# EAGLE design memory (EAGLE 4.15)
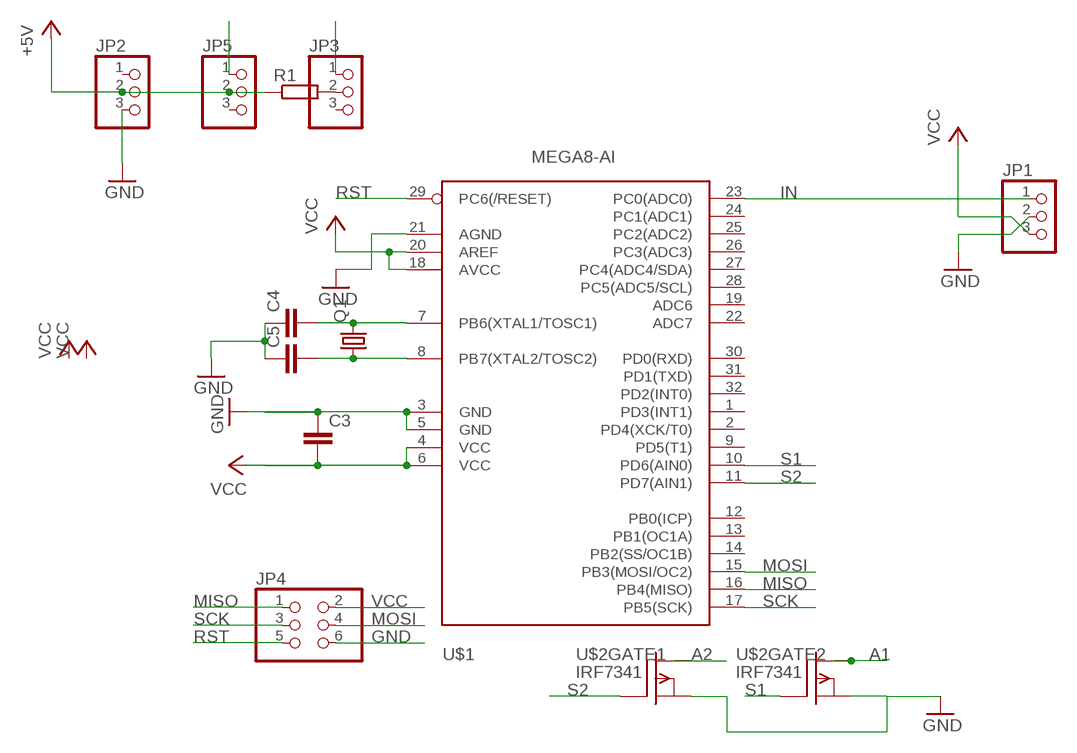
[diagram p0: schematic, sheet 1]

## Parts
C3  C-EUC1206K  [C1206K]
C4  C-EUC1206K  [C1206K]
C5  C-EUC1206K  [C1206K]
JP1  PINHD-1X3  [1X03]
JP2  PINHD-1X3  [1X03]
JP3  PINHD-1X3  [1X03]
JP4  PINHD-2X3  [2X03]
JP5  PINHD-1X3  [1X03]
Q1  CRYTALHC49U-V  [HC49U-V]
R1  R-EU_R1206  [R1206]
U$1  MEGA8-AI  [TQFP32-08]
U$2  IRF7341  [SO-8]

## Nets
+5V: JP2.2 JP5.2 R1.1
A1: JP3.1 U$2.5(GATE2:D1) U$2.6(GATE2:D)
A2: JP5.1 U$2.7(GATE1:D1) U$2.8(GATE1:D)
GND: C3.1 C4.1 C5.1 JP1.2 JP2.3 JP4.6 U$1.3(GND) U$1.5(GND) U$1.21(AGND) U$2.1(GATE1:S) U$2.3(GATE2:S)
IN: JP1.1 U$1.23(PC0(ADC0))
MISO: JP4.1 U$1.16(PB4(MISO))
MOSI: JP4.4 U$1.15(PB3(MOSI/OC2))
N$1: C4.2 Q1.2 U$1.7(PB6(XTAL1/TOSC1))
N$2: C5.2 Q1.1 U$1.8(PB7(XTAL2/TOSC2))
N$7: JP3.2 R1.2
RST: JP4.5 U$1.29(PC6(/RESET))
S1: U$1.10(PD6(AIN0)) U$2.4(GATE2:G)
S2: U$1.11(PD7(AIN1)) U$2.2(GATE1:G)
SCK: JP4.3 U$1.17(PB5(SCK))
VCC: C3.2 JP1.3 JP4.2 U$1.4(VCC) U$1.6(VCC) U$1.18(AVCC) U$1.20(AREF)
Unconnected: JP2.1 JP3.3 JP5.3 U$1.1(PD3(INT1)) U$1.2(PD4(XCK/T0)) U$1.9(PD5(T1)) U$1.12(PB0(ICP)) U$1.13(PB1(OC1A)) U$1.14(PB2(SS/OC1B)) U$1.19(ADC6) U$1.22(ADC7) U$1.24(PC1(ADC1)) U$1.25(PC2(ADC2)) U$1.26(PC3(ADC3)) U$1.27(PC4(ADC4/SDA)) U$1.28(PC5(ADC5/SCL)) U$1.30(PD0(RXD)) U$1.31(PD1(TXD)) U$1.32(PD2(INT0))

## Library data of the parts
C3-C5 = rcl:C-EU: CAPACITOR, European symbol
JP1-JP3 JP5 = pinhead:PINHD-1X3: PIN HEADER
JP4 = pinhead:PINHD-2X3: PIN HEADER
Q1 = crystal:CRYTAL: CRYSTAL
R1 = rcl:R-EU_: RESISTOR, European symbol
U$1 = avr:MEGA8: MICROCONTROLLER 8 Kbytes FLASH 1 kbytes SRAM 512 bytes EEPROM USART 6-channel 10 bit ADC 2-channel 8 bit ADC
U$2 = transistor-fet:IRF7341

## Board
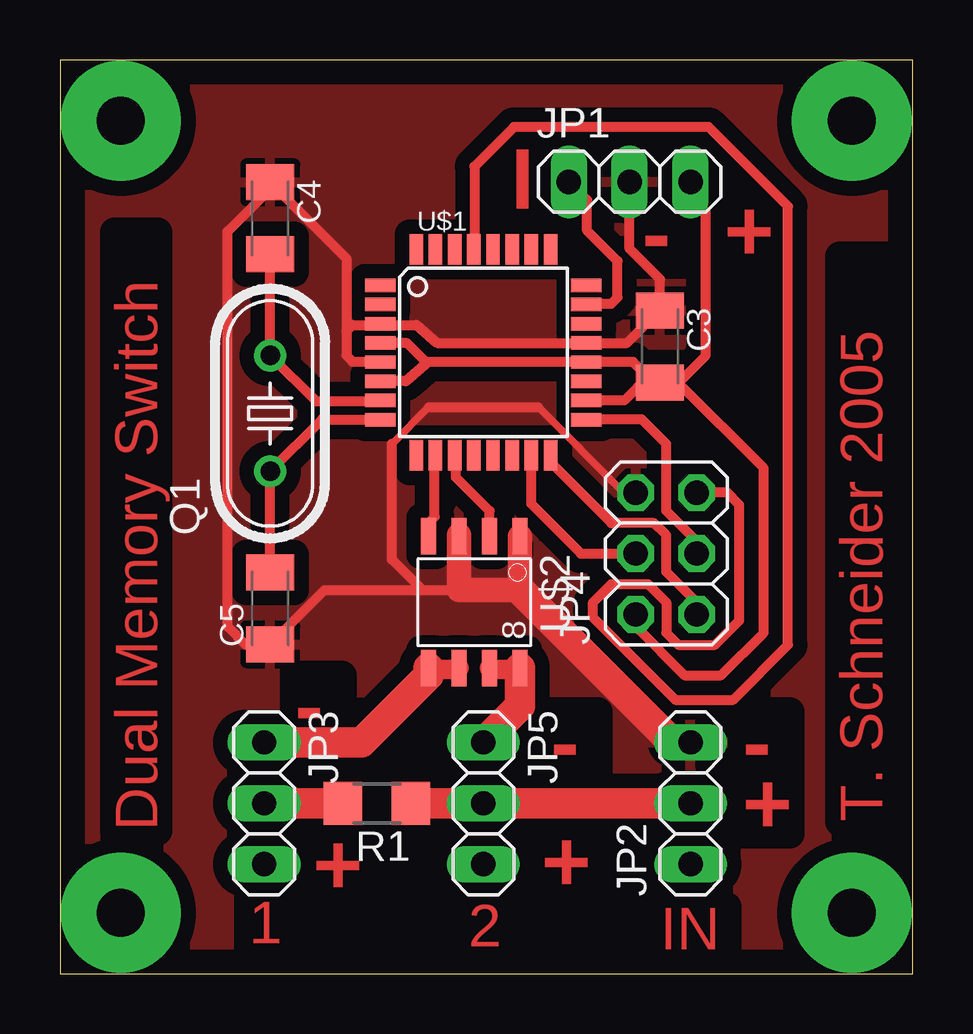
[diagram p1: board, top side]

Size 35.56 x 38.1 mm. Coordinates in mm from the lower left corner, seen from the top.
Outline: 0,0 35.56,0 35.56,38.1 0,38.1 0,0
Copper layers (1*16): Top 0.035mm / dielectric 1.5mm / Bottom 0.035mm
Design rules "default": minimum track width 10mil, minimum drill 24mil, track to track 10mil, track to pad 10mil, pad to pad 8mil, via to via 8mil, smd to smd 8mil, copper to edge 40mil, drill to drill 8mil, minimum pad ring 10mil, minimum via ring 8mil, stop-mask expansion 4mil, vias tented up to drill 0mil, thermal gap 10mil

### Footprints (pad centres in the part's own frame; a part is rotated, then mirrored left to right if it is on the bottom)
C1206K = smd 1.5 x 2: 1 -1.5,0; 2 1.5,0
1X03 = drill 1.016 long: 1 -2.54,0; 2 0,0; 3 2.54,0
2X03 = drill 1.016 octagon: 1 -2.54,-1.27; 2 -2.54,1.27; 3 0,-1.27; 4 0,1.27; 5 2.54,-1.27; 6 2.54,1.27
HC49U-V = drill 0.813 round: 1 -2.413,0; 2 2.413,0
R1206 = smd 1.6 x 1.803: 1 -1.422,0; 2 1.422,0
TQFP32-08 = smd 1.27 x 0.559: 1 -4.293,2.8; 2 -4.293,2; 3 -4.293,1.2; 4 -4.293,0.4; 5 -4.293,-0.4; 6 -4.293,-1.2; 7 -4.293,-2; 8 -4.293,-2.8; 17 4.293,-2.8; 18 4.293,-2; 19 4.293,-1.2; 20 4.293,-0.4; 21 4.293,0.4; 22 4.293,1.2; 23 4.293,2; 24 4.293,2.8 | smd 0.559 x 1.27: 9 -2.8,-4.293; 10 -2,-4.293; 11 -1.2,-4.293; 12 -0.4,-4.293; 13 0.4,-4.293; 14 1.2,-4.293; 15 2,-4.293; 16 2.8,-4.293; 25 2.8,4.293; 26 2,4.293; 27 1.2,4.293; 28 0.4,4.293; 29 -0.4,4.293; 30 -1.2,4.293; 31 -2,4.293; 32 -2.8,4.293
SO-8 = smd 1.524 x 0.61: 1 -2.743,1.27; 2 -2.743,0; 3 -2.743,-1.27; 4 -2.743,-2.54; 5 2.743,-2.54; 6 2.743,-1.27; 7 2.743,0; 8 2.743,1.27

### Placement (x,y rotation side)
C3  25.02,26.16 270 top
C4  8.76,31.5 270 top
C5  8.76,15.24 90 top
JP1  23.75,33.02 0 top
JP2  26.29,7.11 90 top
JP3  8.51,7.11 270 top
JP4  25.27,17.53 90 top
JP5  17.65,7.11 270 top
Q1  8.76,23.37 90 top
R1  13.21,7.11 180 top
U$1  17.65,25.91 0 top
U$2  17.91,15.49 270 top

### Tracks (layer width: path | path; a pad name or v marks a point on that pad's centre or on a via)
+5V
  Top 1.27: JP5.2 JP2.2 | R1.1 JP5.2 | JP5.2 17.65,6.99
A1
  Top 0.813: U$2.6 16.59,12.7 15.42,12.7 U$2.5
  Top 1.27: U$2.5 15.37,12.45 12.57,9.65 JP3.1
A2
  Top 0.813: U$2.7 17.96,12.7 19.13,12.7 U$2.8
  Top 1.27: JP5.1 19.18,11.18 U$2.8
GND
  Top 0.305: 13.84,22.1 15.37,23.62 | 19.94,23.62 23.49,20.07
  Top 0.406: C3.1 24.51,27.69 24.53,27.66 | 23.49,20.07 JP4.6 | 15.37,23.62 19.94,23.62 | 13.84,22.1 13.84,17.27 15.11,16 | 15.11,16 16.64,16 | 13.34,27.05 13.36,27.15 U$1.3 | 13.48,25.51 U$1.5 13.34,25.53 12.19,25.53 11.94,25.78 11.94,26.8 | 24.53,27.66 24.77,27.43 | C3.1 24.53,27.66 | 25.02,27.69 23.64,26.31 U$1.21 15.73,26.31 14.86,27.05 13.34,27.05 | JP1.2 23.75,30.23 25.02,28.96 25.02,27.69 | C3.1 25.02,27.43 25.27,27.18 25.27,27.43 25.02,27.69 | 25.02,27.69 C3.1 | 13.34,27.05 13.34,27.13 U$1.3 | 15.11,16 11.03,16 C5.1 8.66,13.74 8.64,13.72 7.75,13.72 6.99,14.48 6.99,30.95 8.9,32.86 C4.1 11.94,29.82 11.94,26.8 | 11.94,26.8 12.19,27.05 13.34,27.05 | 13.34,27.05 13.36,27.08 U$1.3
  Top 1.016: U$2.1 19.18,16 16.64,16 U$2.3 16.64,18.29
  Top 1.27: 26.54,9.65 JP2.3 25.53,9.65 19.18,16
  pour Top (isolate 0.61): -1.14,39.24 -1.14,-0.89 37.46,-0.89 37.46,39.24
IN
  Top 0.406: U$1.23 21.97,27.94 22.99,27.94 23.24,28.19 23.24,29.72 21.97,30.99 21.97,32.26 JP1.1
MISO
  Top 0.406: U$1.16 20.45,21.33 22.99,18.8 24.77,18.8 25.27,18.29 25.27,16.76 26.54,15.49 JP4.1 26.8,14.73
MOSI
  Top 0.406: U$1.15 19.65,19.59 21.72,17.53 JP4.4 24.26,17.53
N$1
  Top 0.406: U$1.7 13.34,23.88 10.67,23.88 Q1.2 C4.2
N$2
  Top 0.406: U$1.8 13.34,23.11 10.92,23.11 Q1.1 C5.2
N$3  (via drill 2 pad 5)
  other vias: 2.54,35.56
N$4  (via drill 2 pad 5)
  other vias: 2.54,2.54
N$5  (via drill 2 pad 5)
  other vias: 33.02,2.54
N$6  (via drill 2 pad 5)
  other vias: 33.02,35.56
N$7
  Top 1.27: JP3.2 R1.2
RST
  Top 0.406: JP4.5 27.81,20.07 28.32,19.56 28.32,14.73 27.3,13.72 25.78,13.72 25.27,14.22 25.27,15.49 24.51,16.26 22.99,16.26 22.23,15.49 22.23,14.86 25.65,11.43 28.07,11.43 30.35,13.72 30.35,32 27.05,35.31 18.92,35.31 17.27,33.66 17.27,30.18 | 17.27,30.18 17.27,30.1 | 17.27,30.18 U$1.29
S1
  Top 0.406: U$2.4 15.37,18.8 15.62,19.05 15.62,21.59 15.63,21.59 U$1.10
S2
  Top 0.406: U$2.2 17.91,19.3 16.51,20.7 16.51,21.59 | 16.51,21.59 16.43,21.59 U$1.11 16.48,21.61 16.51,21.59
SCK
  Top 0.406: JP4.3 26.54,18.03 25.27,19.3 25.27,22.1 24.26,23.11 21.97,23.11 U$1.17
VCC
  Top 0.406: JP4.2 24,14.48 26.03,12.45 27.56,12.45 29.34,14.22 29.34,21.08 25.78,24.64 | C3.2 24.51,24.89 23.53,23.91 U$1.18 | C3.2 24.51,24.64 | 15.37,25.51 15.26,25.51 14.48,26.29 13.38,26.29 U$1.4 | 15.37,25.51 U$1.20 23.9,25.51 24.77,24.64 24.79,24.66 C3.2 | 15.37,25.51 15.37,25.53 14.42,24.71 U$1.6 | C3.2 25.76,24.66 25.78,24.64 | JP1.3 26.29,32.38 26.92,31.75 26.92,25.78 25.78,24.64

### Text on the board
Top: I | - | + | - | - | - | T. Schneider 2005 | Dual Memory Switch | + | + | + | 1 | 2 | IN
